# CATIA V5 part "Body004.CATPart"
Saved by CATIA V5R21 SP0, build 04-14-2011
Part number: Body004
Definition: design
Nomenclature: Body004
Source: Unknown
Bounding box of the stored display mesh (mm): x -3.2 to 3.2, y -0.1 to 0.1, z 0 to 0.67
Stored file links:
  C:\Users\beatr\OneDrive\Documents\UNB\2026_1\Pi1\Componentes eletronicos\Encoder\Body004.CATPart
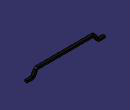
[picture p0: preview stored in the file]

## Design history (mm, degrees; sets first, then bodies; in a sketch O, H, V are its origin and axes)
Body1 "MANIFOLD_SOLID_BREP #3354" (main body)
  Solid1: solid without history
